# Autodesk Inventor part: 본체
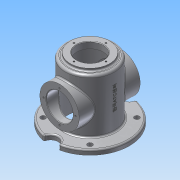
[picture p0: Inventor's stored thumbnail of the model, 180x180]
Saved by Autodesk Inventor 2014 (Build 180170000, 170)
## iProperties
Created: 2018-04
Part Number: 본체
Material: 알루미늄 6061
Document SubType Name: Modeling
Designer: user
Density: 2.71 g/cm^3
Appearance: 알루미늄 - 평지
Mass: 1151.3 g
Surface Area: 1200.36 cm^2
Volume: 424.833 cm^3
Author: user
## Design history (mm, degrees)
sketch "스케치1"
  geometry: C1 r 50 at (0, 0); 1 further point
  constraints: 1 centre point, 1 coincident
  dimensions: "d0" = 100 diameter of C1
extrude "돌출1" new body sketch "스케치1" distance "d1" = 128; taper "d2" = 0 deg
feature "쉘1" dims "d3" = 8, "d4" = 5
sketch "스케치2"
  geometry: C1 r 50 at (0, 0) reference; C2 r 40 at (0, 0)
  constraints: 1 centre point, 1 coincident
  dimensions: "d5" = 80 diameter of C2
extrude "돌출2" join sketch "스케치2" distance "d6" = 5; taper "d7" = 0 deg
sketch "스케치3"
  geometry: C1 r 40 at (0, 0) reference; C2 r 27 at (0, 0)
  constraints: 1 centre point, 1 coincident
  dimensions: "d8" = 54 diameter of C2
extrude "돌출3" cut sketch "스케치3" distance "d9" = 13; taper "d10" = 0 deg
node "작업 평면1"
sketch "스케치4"
  geometry: L1 (0, 0)-(-47.73, 47.73); L2 (0, 0)-(67.5, 0); C1 r 45 at (0, 0) reference; C2 r 50 at (0, 0) reference; C3 r 45 at (0, 0) reference; C4 r 50 at (0, 0) reference; C5 r 5 at (-47.73, 47.73); C6 r 5 at (-47.73, -47.73); C7 r 5 at (47.73, -47.73); C8 r 5 at (47.73, 47.73); A1 r 15 centre (80, 0) between (78.594, 14.934) and (78.594, -14.934); A2 r 15 centre (-80, 0) between (-78.594, -14.934) and (-78.594, 14.934); A3 r 80 centre (0, 0) between (-78.594, -14.934) and (78.594, -14.934); A4 r 80 centre (0, 0) between (78.594, 14.934) and (-78.594, 14.934); 1 further point
  constraints: 8 centre point, 8 point on circle, 4 end point, 2 coincident, 1 equal length, 1 horizontal, 9 other
  dimensions: "d13" = 30 diameter of A1; "d14" = 30 diameter of A2; "d15" = 67.5 distance of L1.start L1.end; "d16" = 135 deg angle of L2 L1; "d17" = 10 diameter of C5; "d20" = 360 deg dimension on L1.start C5.centre (derived); "d22" = 80 radius of A4; "d23" = 80 radius of A3; "d24" = 0 distance from line of A1.centre L2; "d25" = 56.56854 distance from line of A1.centre L1; "d26" = 14.93394 distance from line of A2.end L2; "d27" = 14.93394 distance from line of A2.start L2
extrude "돌출4" join sketch "스케치4" distance "d28" = 10; taper "d29" = 0 deg
node "작업 평면2"
sketch "스케치5"
  geometry: C1 r 40 at (0, 68); 1 further point
  constraints: 1 centre point, 1 vertical alignment
  dimensions: "d31" = 80 diameter of C1; "d32" = 68 distance of point (0, 0) C1.centre
extrude "돌출5" join sketch "스케치5" stored distance "d33" = 80 (= d31); taper "d34" = 0 deg
sketch "스케치6"
  geometry: C1 r 40 at (0, 0) reference; C2 r 27 at (0, 0); 1 further point
  constraints: 1 centre point, 1 coincident
  dimensions: "d35" = 54 diameter of C2
extrude "돌출6" cut sketch "스케치6" distance "d36" = 100; taper "d37" = 0 deg
sketch "스케치7"
  geometry: C1 r 27 at (0, 0) reference; 5 further points
  constraints: 1 horizontal alignment, 5 other
  dimensions: "d38" = 32.5 distance of C1.centre point (32.5, 0); "d41" = 360 deg dimension on C1.centre point (32.5, 0) (derived)
hole "구멍1" sketch "스케치7" at (32.5, 0), (0, 32.5), (-32.5, 0), (0, -32.5) diameter "d43" = 3.242; stored, may be unused: countersink angle "d47" = 90 deg, drill point angle "d49" = 118 deg; dims "d44" = 8, "d45" = 4, "d46" = 2, "d48" = 10
sketch "스케치8"
  geometry: C1 r 27 at (0, 0) reference; 4 further points
  constraints: 1 vertical alignment, 5 other
  dimensions: "d50" = 32.5 distance of point (0, 32.5) C1.centre; "d53" = 360 deg dimension on C1.centre point (0, 32.5) (derived)
hole "구멍2" sketch "스케치8" at (0, 32.5), (-32.5, 0), (0, -32.5), (32.5, 0) diameter "d55" = 3.242; stored, may be unused: countersink angle "d59" = 90 deg, drill point angle "d61" = 118 deg; dims "d56" = 8, "d57" = 4, "d58" = 2, "d60" = 10
node "작업 평면3"
sketch "스케치9"
  geometry: L1 (-78.594, 8)-(78.594, 8) reference; 2 further points
  constraints: 1 vertical alignment, 1 other
  dimensions: "d63" = 70 distance from line of point (0, 78) L1
feature "엠보싱1" sketch "스케치9" dims "d1" = 128, "d64" = 0.5, "d65" = 0
fillet "모깎기1" dims "d66" = 3
fillet "모깎기2" dims "d67" = 3
fillet "모깎기3" dims "d68" = 3
fillet "모깎기4" dims "d69" = 3
fillet "모깎기5" dims "d70" = 5
fillet "모깎기6" dims "d71" = 3
fillet "모깎기7" dims "d72" = 3
chamfer "모따기1" distance "d73" = 1; stored, may be unused: second distance "d74" = 2, angle "d75" = 45 deg
chamfer "모따기2" distance "d76" = 1; stored, may be unused: second distance "d77" = 2, angle "d78" = 45 deg
fillet "모깎기8" dims "d79" = 3
fillet "모깎기9" dims "d80" = 3
node "솔리드1"
mirror "대칭1"
mirror "대칭2"
node "절단 모서리 투영1"
node "절단 모서리 투영2"
other parameters: "d11" = -8, "d30" = 62
